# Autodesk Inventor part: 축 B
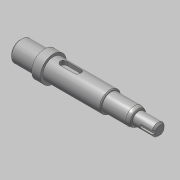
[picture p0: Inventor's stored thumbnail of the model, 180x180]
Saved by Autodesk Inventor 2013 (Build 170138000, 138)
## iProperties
Created: 2020-04
Part Number: 축 B
Material: 강철, 연강
Document SubType Name: Modeling
Designer: mduedu
Density: 1 g/cm^3
Author: mduedu
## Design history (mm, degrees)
sketch "스케치1"
  geometry: L1 (0, 0)-(14, 0); L2 (14, 0)-(14, 6); L3 (14, 6)-(0, 6); L4 (0, 6)-(0, 0); L5 (14, 0)-(19, 0); L6 (19, 0)-(19, 7.5); L7 (19, 7.5)-(14, 7.5); L8 (14, 7.5)-(14, 0); L9 (19, 0)-(52, 0); L10 (52, 0)-(52, 6); L11 (52, 6)-(19, 6); L12 (19, 6)-(19, 0); L13 (52, 0)-(68, 0); L14 (68, 0)-(68, 5); L15 (68, 5)-(52, 5); L16 (52, 5)-(52, 0); L17 (68, 0)-(80, 0); L18 (80, 0)-(80, 3.5); L19 (80, 3.5)-(68, 3.5); L20 (68, 3.5)-(68, 0)
  constraints: 40 end point, 10 parallel, 5 horizontal, 5 perpendicular
  dimensions: "d0" = 80 distance between parallel lines of L18 L4; "d2" = 14 distance of L2.end L3.end; "d3" = 5 distance of L6.end L7.end; "d5" = 7 diameter of L19 L17; "d6" = 10 diameter of L15 L13; "d7" = 12 diameter of L11 L9; "d8" = 12 diameter of L3 L1; "d9" = 15 diameter of L7 L5; "d35" = 16 distance of L14.end L15.end; "d36" = 52 distance between parallel lines of L10 L4
revolve "회전1" sketch "스케치1" stored, may be unused: angle "d11" = 90 deg
sketch "스케치2"
  geometry: L1 (0, 6)-(0, -6) reference; L2 (0, -6)-(-14, -6) reference; L3 (-14, -6)-(-14, -7.5) reference; L4 (-14, -7.5)-(-19, -7.5) reference; L5 (-19, -7.5)-(-19, -6) reference; L6 (-19, -6)-(-52, -6) reference; L7 (-52, -6)-(-52, -5) reference; L8 (-52, -5)-(-68, -5) reference; L9 (-68, -5)-(-68, -3.5) reference; L10 (-68, -3.5)-(-80, -3.5) reference; L11 (-80, -3.5)-(-80, 3.5) reference; L12 (-80, 3.5)-(-68, 3.5) reference; L13 (-68, 3.5)-(-68, 5) reference; L14 (-68, 5)-(-52, 5) reference; L15 (-52, 5)-(-52, 6) reference; L16 (-52, 6)-(-19, 6) reference; L17 (-19, 6)-(-19, 7.5) reference; L18 (-19, 7.5)-(-14, 7.5) reference; L19 (-14, 7.5)-(-14, 6) reference; L20 (-14, 6)-(0, 6) reference; L21 (-80, 3.5)-(-72, 3.5); L22 (-72, 3.5)-(-72, 2.3); L23 (-72, 2.3)-(-80, 2.3); L24 (-80, 2.3)-(-80, 3.5); 1 further point
  constraints: 8 end point, 2 parallel, 1 horizontal, 1 perpendicular
  dimensions: "d37" = 8 distance of L22.end L23.end; "d38" = 1.2 distance of L21.end L22.end
extrude "돌출1" cut sketch "스케치2" stored distance "d14" = 2; taper "d15" = 0 deg
fillet "모깎기1" dims "d16" = 1
sketch "스케치3"
  geometry: L1 (0, -6)-(0, 6) reference; L2 (0, 6)-(14, 6) reference; L3 (14, 6)-(14, 7.5) reference; L4 (14, 7.5)-(19, 7.5) reference; L5 (19, 7.5)-(19, 6) reference; L6 (19, 6)-(52, 6) reference; L7 (52, 6)-(52, 5) reference; L8 (52, 5)-(68, 5) reference; L9 (68, 5)-(68, 3.5) reference; L10 (68, 3.5)-(80, 3.5) reference; L11 (80, 3.5)-(80, -3.5) reference; L12 (80, -3.5)-(68, -3.5) reference; L13 (68, -3.5)-(68, -5) reference; L14 (68, -5)-(52, -5) reference; L15 (52, -5)-(52, -6) reference; L16 (52, -6)-(19, -6) reference; L17 (19, -6)-(19, -7.5) reference; L18 (19, -7.5)-(14, -7.5) reference; L19 (14, -7.5)-(14, -6) reference; L20 (14, -6)-(0, -6) reference; L21 (23, 6)-(35, 6); L22 (35, 6)-(35, 3.5); L23 (35, 3.5)-(23, 3.5); L24 (23, 3.5)-(23, 6); 1 further point
  constraints: 8 end point, 2 parallel, 1 horizontal, 1 perpendicular, 1 point on line
  dimensions: "d17" = 12 distance of L22.end L23.end; "d18" = 2.5 distance of L21.end L22.end; "d19" = 4 distance from line of L24 L4.end
extrude "돌출2" cut sketch "스케치3" stored distance "d20" = 4; taper "d21" = 0 deg
fillet "모깎기2" dims "d22" = 2
chamfer "모따기1" distance "d23" = 1; stored, may be unused: second distance "d24" = 2, angle "d25" = 45 deg
chamfer "모따기2" distance "d26" = 0.5; stored, may be unused: second distance "d27" = 2, angle "d28" = 45 deg
fillet "모깎기3" dims "d29" = 0.3
chamfer "모따기3" distance "d30" = 1.39; stored, may be unused: second distance "d31" = 2, angle "d32" = 30 deg
fillet "모깎기4" dims "d33" = 4, "d34" = 0.5
node "솔리드1"
node "절단 모서리 투영2"
node "절단 모서리 투영3"
